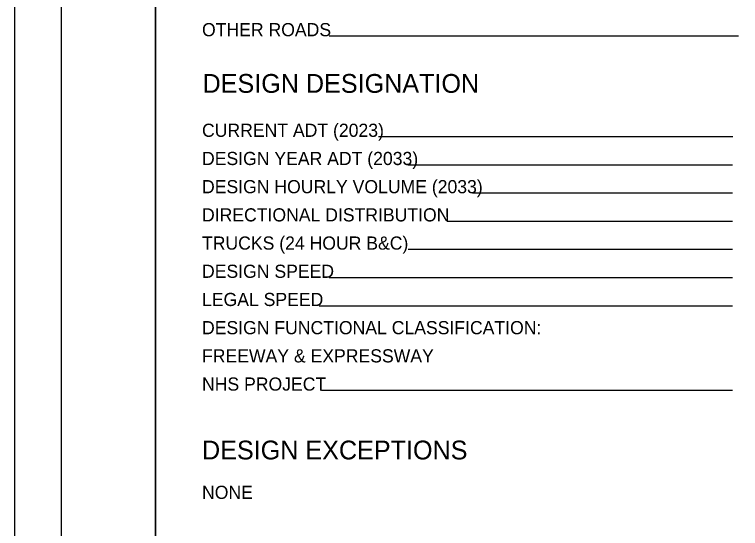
# Model space of a CAD drawing. Extents: x 0 to 34, y 0 to 22.
# Drawn here: x 0 to 7.72, y 5.64 to 11.11 of the extents above; entities that cross this region are included whole.
import ezdxf

# ---------------------------------------------------------------- set-up
doc = ezdxf.new("R2010")
doc.units = 0
for name, color, linetype in [('SH_Border', 7, 'Continuous'), ('SH_Cut_Line', 7, 'Continuous'), ('SH_Data', 7, 'Continuous')]:
    doc.layers.add(name, color=color, linetype=linetype)

msp = doc.modelspace()

# ---------------------------------------------------------------- linework, layer by layer
at = {"layer": 'SH_Border'}
for points in [[(0.5, 21.5), (1.5, 21.5), (1.5, 0.5), (0.5, 0.5)], [(1.5, 21.5), (33.5, 21.5), (33.5, 0.5), (1.5, 0.5)]]:
    msp.add_lwpolyline(points, close=True, dxfattribs=at)
at = {"layer": 'SH_Cut_Line'}
msp.add_lwpolyline([(0, 0), (34, 0), (34, 22), (0, 22)], close=True, dxfattribs=at)
at = {"layer": 'SH_Data'}
for p, q in [((7.7, 10.8767), (3.3471, 10.8767)), ((7.6424, 9.8062), (3.871, 9.8062)), ((7.6368, 9.5062), (4.1885, 9.5062)), ((7.6368, 9.2062), (4.8723, 9.2062)), ((7.6368, 8.9062), (4.6037, 8.9062)), ((7.6368, 8.6062), (4.1885, 8.6062)), ((7.6368, 8.3062), (3.346, 8.3062)), ((7.6368, 8.0062), (3.2422, 8.0062)), ((7.6368, 7.1062), (3.2669, 7.1062))]:
    msp.add_line(p, q, dxfattribs=at)

# ---------------------------------------------------------------- texts
for s, height, p in [('OTHER ROADS', 0.14, (1.9944, 10.8767)), ('DESIGN DESIGNATION', 0.2, (2, 10.2747)), ('CURRENT ADT (2023)', 0.14, (1.9944, 9.8062)), ('DESIGN YEAR ADT (2033)', 0.14, (1.9944, 9.5062)), ('DESIGN HOURLY VOLUME (2033)', 0.14, (1.9944, 9.2062)), ('DIRECTIONAL DISTRIBUTION', 0.14, (1.9944, 8.9062)), ('TRUCKS (24 HOUR B&C)', 0.14, (1.9944, 8.6062)), ('DESIGN SPEED', 0.14, (1.9944, 8.3062)), ('LEGAL SPEED', 0.14, (1.9944, 8.0062)), ('DESIGN FUNCTIONAL CLASSIFICATION:', 0.14, (1.9944, 7.7062)), ('FREEWAY & EXPRESSWAY', 0.14, (1.9944, 7.4062)), ('NHS PROJECT', 0.14, (1.9944, 7.1062)), ('DESIGN EXCEPTIONS', 0.2, (1.9944, 6.3744)), ('NONE', 0.14, (1.9944, 5.9544))]:
    msp.add_text(s, height=height, dxfattribs=at).set_placement(p)

doc.saveas('drawing.dxf')
